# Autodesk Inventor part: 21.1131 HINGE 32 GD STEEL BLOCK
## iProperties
Created: 2007-01
Part Number: 21.1131 HINGE 32 GD STEEL BLOCK
Document SubType Name: Modeling
Designer: Andy Moles
Material: Steel
Density: 7.85 g/cm^3
Author: Andy Moles
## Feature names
1. Base1
